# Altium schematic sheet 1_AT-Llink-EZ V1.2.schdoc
size 309 x 223 mm; Symbol: Artery_A4; Device: Artery_A4; Company: Artery Technology; Drawed: SD; Version: 1.1; Page Size: A4; @Project Name: p_AT-START-F437; @Page Count: 5; @Update Date: 2023-04-14 17:11:57; @Create Date: 2022-12-01; @Schematic Name: AT-START-F437 V1.1; @Page No: 1; @Page Name: AT-Llink-EZ V1.2
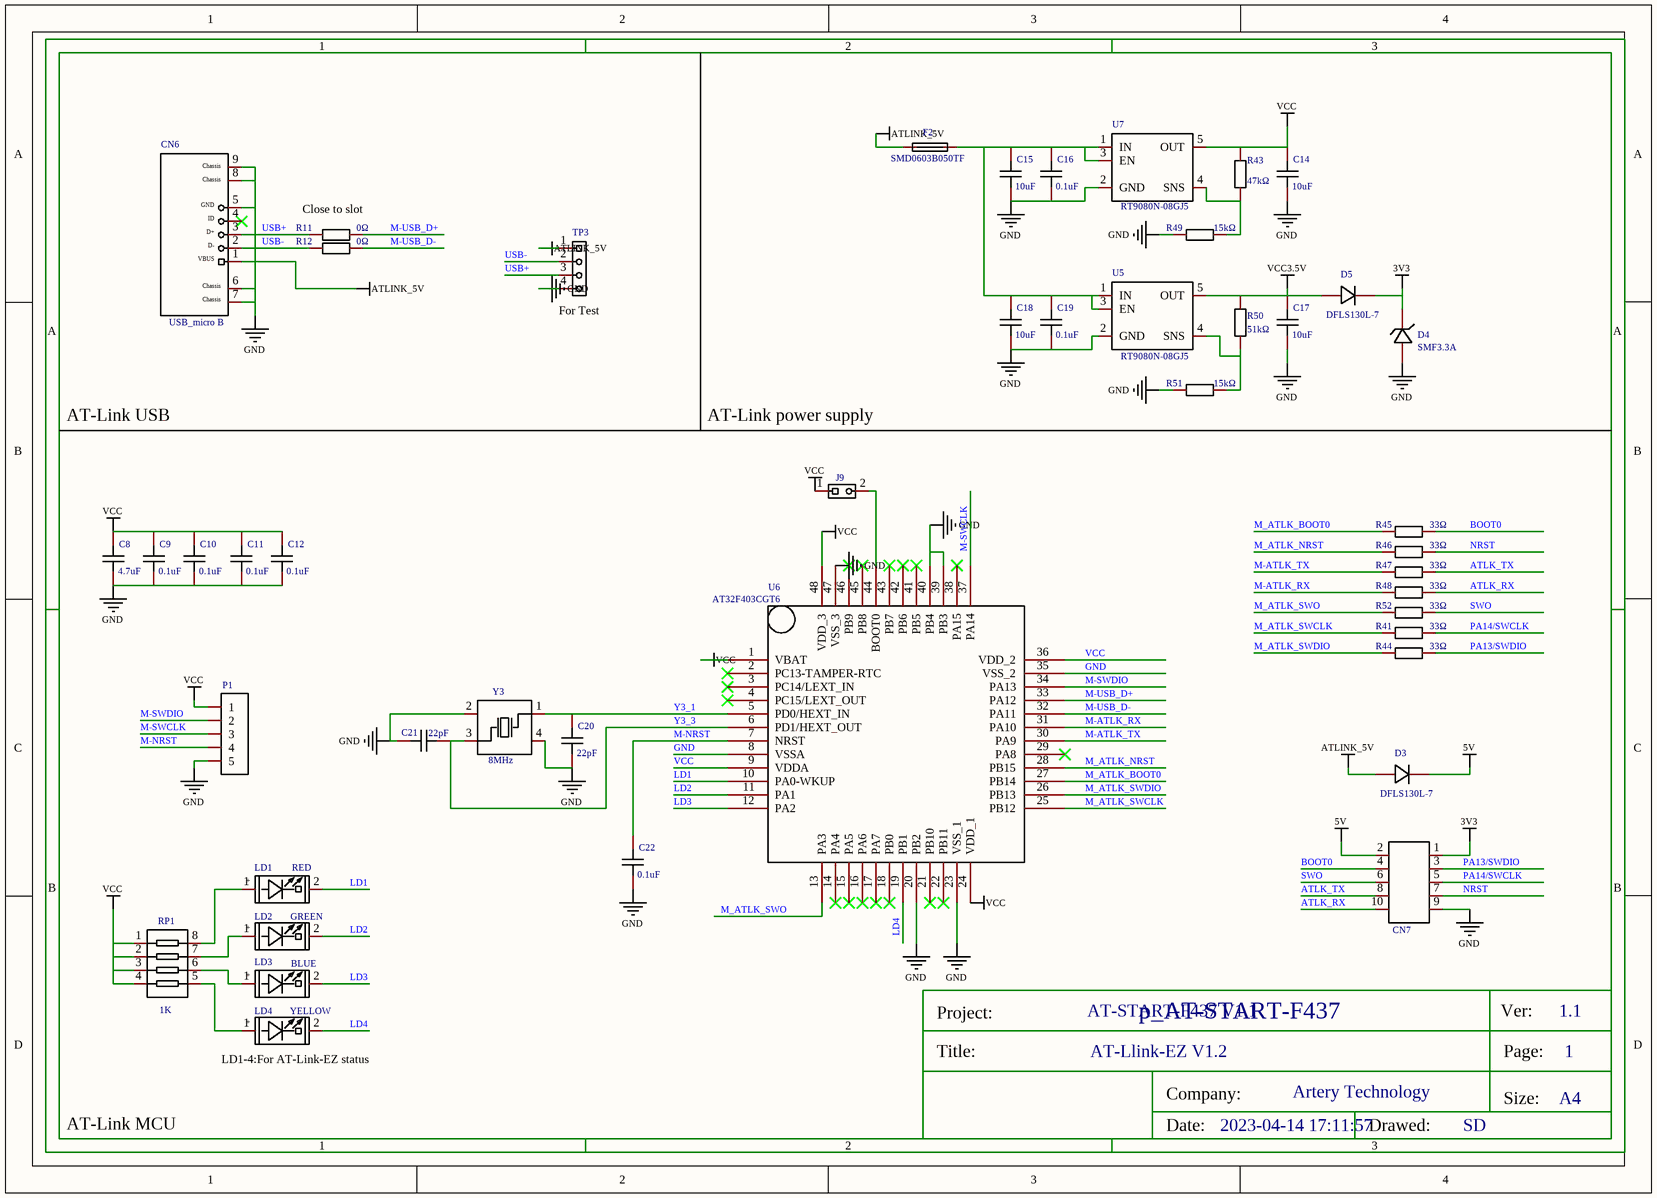
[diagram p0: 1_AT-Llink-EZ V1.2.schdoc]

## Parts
C8  4.7uF  [0603_C-M]
C9  0.1uF  [0603_C-M]
C10  0.1uF  [0603_C-M]
C11  0.1uF  [0603_C-M]
C12  0.1uF  [0603_C-M]
C14  10uF  [0603_C-M]
C15  10uF  [0603_C-M]
C16  0.1uF  [0603_C-M]
C17  10uF  [0603_C-M]
C18  10uF  [0603_C-M]
C19  0.1uF  [0603_C-M]
C20  22pF  [0603_C-M]
C21  22pF  [0603_C-M]
C22  0.1uF  [0603_C-M]
CN6  USB_micro B  [USB_MIC_DIP]
CN7  CON1  [HDR2X5]  (value not drawn)
D3  DFLS130L-7  [POWERDI-123_L2.8-W1.8-LS3.7-RD]
D4  SMF3.3A  [SOD-123_L2.8-W1.8-LS3.7-RD]
D5  DFLS130L-7  [POWERDI-123_L2.8-W1.8-LS3.7-RD]
F2  SMD0603B050TF  [R0603]
J9  1X2P,Male,DIP_2.54  [HDR1X2]  (value not drawn)
LD1  RED  [LED0603]
LD2  GREEN  [LED0603]
LD3  BLUE  [LED0603]
LD4  YELLOW  [LED0603]
P1  HDR-M-2.54_1x5  [HDR-M-2.54_1X5]  (value not drawn)
R11  0Ω  [R0603]
R12  0Ω  [R0603]
R41  33Ω  [R0603]
R43  47kΩ  [R0603]
R44  33Ω  [R0603]
R45  33Ω  [R0603]
R46  33Ω  [R0603]
R47  33Ω  [R0603]
R48  33Ω  [R0603]
R49  15kΩ  [R0603]
R50  51kΩ  [R0603]
R51  15kΩ  [R0603]
R52  33Ω  [R0603]
RP1  1K  [0603*4,8P4R]
TP3  1X4P_2.54F  [HDR1X4 - TOP]  (value not drawn)
U5  RT9080N-08GJ5  [SOT-23-5]
U6  AT32F403CGT6  [LQFP48 - 2]
U7  RT9080N-08GJ5  [SOT-23-5]
Y3  8MHz  [OSC-SMD_4P-L5.0-W3.2-BL]

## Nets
3V3: CN7.1 D4.1 D5.1
5V: CN7.2 D3.1
ATLINK_5V: CN6.1(VBUS) D3.2 F2.1 TP3.1
GND: C8.2 C9.2 C10.2 C11.2 C12.2 C14.2 C15.2 C16.2 C17.2 C18.2 C19.2 C20.2 C21.1 C22.2 CN6.5(GND) CN6.6 CN6.7 CN6.8 CN6.9 CN7.9 D4.2 P1.5 R49.2 R51.2 TP3.4 U5.2(GND) U6.8(VSSA) U6.20(PB2) U6.23(VSS_1) U6.35(VSS_2) U6.39(PB3) U6.40(PB4) U6.47(VSS_3) U7.2(GND) Y3.2(GND) Y3.4(GND)
VCC: C8.1 C9.1 C10.1 C11.1 C12.1 C14.1 J9.1 P1.1 R43.2 RP1.1 RP1.2 RP1.3 RP1.4 U6.1(VBAT) U6.9(VDDA) U6.24(VDD_1) U6.36(VDD_2) U6.48(VDD_3) U7.5(OUT)
VCC3.5V: C17.1 D5.2 R50.2 U5.5(OUT)
ATLK_RX: CN7.10 R48.1
ATLK_TX: CN7.8 R47.1
BOOT0: CN7.4 R45.1
LD1: LD1.2(CATHODE) U6.10(PA0-WKUP)
LD2: LD2.2(CATHODE) U6.11(PA1)
LD3: LD3.2(CATHODE) U6.12(PA2)
LD4: LD4.2(CATHODE) U6.19(PB1)
M-ATLK_RX: R48.2 U6.31(PA10)
M-ATLK_TX: R47.2 U6.30(PA9)
M-NRST: C22.1 P1.4 U6.7(NRST)
M-SWCLK: P1.3 U6.37(PA14)
M-SWDIO: P1.2 U6.34(PA13)
M-USB_D+: R11.2 U6.33(PA12)
M-USB_D-: R12.2 U6.32(PA11)
M_ATLK_BOOT0: R45.2 U6.27(PB14)
M_ATLK_NRST: R46.2 U6.28(PB15)
M_ATLK_SWCLK: R41.2 U6.25(PB12)
M_ATLK_SWDIO: R44.2 U6.26(PB13)
M_ATLK_SWO: R52.2 U6.13(PA3)
NRST: CN7.7 R46.1
PA13/SWDIO: CN7.3 R44.1
PA14/SWCLK: CN7.5 R41.1
SWO: CN7.6 R52.1
USB+: CN6.3(D+) R11.1 TP3.3
USB-: CN6.2(D-) R12.1 TP3.2
Y3_1: C20.1 U6.5(PD0/HEXT_IN) Y3.1(OSC1)
Y3_3: C21.2 U6.6(PD1/HEXT_OUT) Y3.3(OSC2)
NetC15_1: C15.1 C16.1 C18.1 C19.1 F2.2 U5.1(IN) U5.3(EN) U7.1(IN) U7.3(EN)
NetJ9_2: J9.2 U6.44(BOOT0)
NetLD1_1: LD1.1(ANODE) RP1.8
NetLD2_1: LD2.1(ANODE) RP1.7
NetLD3_1: LD3.1(ANODE) RP1.6
NetLD4_1: LD4.1(ANODE) RP1.5
NetR43_1: R43.1 R49.1 U7.4(SNS)
NetR50_1: R50.1 R51.1 U5.4(SNS)

Not connected (* = marked no-connect by the designer): CN6 4(ID)*; U6 2(PC13-TAMPER-RTC)* 3(PC14/LEXT_IN)* 4(PC15/LEXT_OUT)* 14(PA4)* 15(PA5)* 16(PA6)* 17(PA7)* 18(PB0)* 21(PB10)* 22(PB11)* 29(PA8)* 38(PA15)* 41(PB5)* 42(PB6)* 43(PB7)* 45(PB8)* 46(PB9)*

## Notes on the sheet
- (near R11) Close to slot
- (near TP3) For Test
- AT-Link USB
- AT-Link power supply
- (near LD4) LD1-4:For AT-Link-EZ status
- AT-Link MCU

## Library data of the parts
C8 = 4.7uF: Convert to PCB: yes
C9-C12 C16 C19 C22 = 0.1uF: Convert to PCB: yes
C14 C15 C17 C18 = 10uF: Convert to PCB: yes
C20 C21 = 22pF: Convert to PCB: yes
CN6 = USB_micro B: Convert to PCB: yes
CN7 = CON1: Convert to PCB: yes
D3 D5 = DFLS130L-7: Manufacturer: Diodes Incorporated; Paste Type: expand; Convert to PCB: yes
D4 = SMF3.3A: Manufacturer: DOWO; Paste Type: expand; Convert to PCB: yes
F2 = SMD0603B035TF: Manufacturer: Brightking Elec (TAIWAN); Paste Type: expand; Convert to PCB: yes
J9 = 1X2P,Male,DIP_2.54: Convert to PCB: yes
LD1 = RED: Convert to PCB: yes
LD2 = GREEN: Convert to PCB: yes
LD3 = BLUE: Convert to PCB: yes
LD4 = YELLOW: Convert to PCB: yes
P1 = HDR-M-2.54_1x5: Convert to PCB: yes
R11 R12 = 0603WAF0000T5E: 电阻类型:厚膜电阻;阻值:0Ω;精度:±1%;功率:100mW;最大工作电压:75V;工作温度范围:-55℃~+155℃;; Manufacturer: UNI-ROYAL(厚声); Add into BOM: yes; Tolerance: ±1%; Power(Watts): 100mW; Overload Voltage (Max): 75V
R41 R44-R48 R52 = 0603WAF330JT5E: 电阻类型:厚膜电阻;阻值:33Ω;精度:±1%;功率:100mW;温度系数:±100ppm/℃;最大工作电压:75V;工作温度范围:-55℃~+155℃;; Manufacturer: UNI-ROYAL(厚声); Add into BOM: yes; Tolerance: ±1%; Power(Watts): 100mW; Overload Voltage (Max): 75V
R43 = 0603WAF4702T5E: 电阻类型:厚膜电阻;阻值:47kΩ;精度:±1%;功率:100mW;温度系数:±100ppm/℃;最大工作电压:75V;工作温度范围:-55℃~+155℃;; Manufacturer: UNI-ROYAL(厚声); Add into BOM: yes; Tolerance: ±1%; Power(Watts): 100mW; Overload Voltage (Max): 75V
R49 R51 = 0603WAF1502T5E: 电阻类型:厚膜电阻;阻值:15kΩ;精度:±1%;功率:100mW;温度系数:±100ppm/℃;最大工作电压:75V;工作温度范围:-55℃~+155℃;; Manufacturer: UNI-ROYAL(厚声); Add into BOM: yes; Tolerance: ±1%; Power(Watts): 100mW; Overload Voltage (Max): 75V
R50 = 0603WAF5102T5E: 电阻类型:厚膜电阻;阻值:51kΩ;精度:±1%;功率:100mW;温度系数:±100ppm/℃;最大工作电压:75V;工作温度范围:-55℃~+155℃;; Manufacturer: UNI-ROYAL(厚声); Add into BOM: yes; Tolerance: ±1%; Power(Watts): 100mW; Overload Voltage (Max): 75V
RP1 = 1K: Convert to PCB: yes
TP3 = 1X4P_2.54F: Convert to PCB: yes
U5 U7 = RT9080N-08GJ5: Convert to PCB: yes
U6 = AT32F403CGT6: Convert to PCB: yes
Y3 = SMD-5032_4P8M20pf20ppm: Manufacturer: TAE; Paste Type: recommend; Convert to PCB: yes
